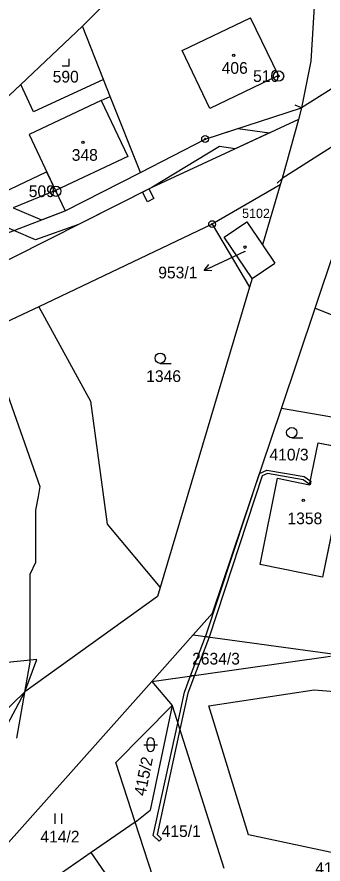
# Model space of a CAD drawing. Extents: x -439246 to -433691, y -1130252 to -1121148.
# Drawn here: x -437746.8 to -437702.2, y -1124070.1 to -1123946.9 of the extents above; entities that cross this region are included whole.
import ezdxf

# ---------------------------------------------------------------- set-up
doc = ezdxf.new("R2010")
doc.units = 0
for name, color, linetype in [('Vrstva 1', 7, 'Continuous'), ('Vrstva 16', 7, 'Continuous'), ('Vrstva 17', 7, 'Continuous'), ('Vrstva 18', 7, 'Continuous'), ('Vrstva 19', 7, 'Continuous'), ('Vrstva 24', 7, 'Continuous'), ('Vrstva 25', 7, 'Continuous'), ('Vrstva 26', 7, 'Continuous'), ('Vrstva 3', 7, 'Continuous'), ('Vrstva 30', 7, 'Continuous'), ('Vrstva 37', 7, 'Continuous'), ('Vrstva 4', 7, 'Continuous'), ('Vrstva 52', 7, 'Continuous')]:
    doc.layers.add(name, color=color, linetype=linetype)

msp = doc.modelspace()

# ---------------------------------------------------------------- linework, layer by layer
at = {"layer": 'Vrstva 1'}
for p, q in [((-437705.84, -1123961.83), (-437708.21, -1123970.37)), ((-437703.39, -1123989.26), (-437690.8, -1123994.18)), ((-437704.24, -1124014.94), (-437702.97, -1124008.81)), ((-437702.97, -1124008.81), (-437698.5, -1124009.7)), ((-437698.5, -1124009.7), (-437702.33, -1124028.36)), ((-437711.41, -1124026.51), (-437708.88, -1124013.98)), ((-437708.88, -1124013.98), (-437704.24, -1124014.94)), ((-437702.33, -1124028.36), (-437711.41, -1124026.51))]:
    msp.add_line(p, q, dxfattribs=at)
for points in [[(-437737.21, -1123948.27), (-437731.59, -1123942.56)], [(-437703.45, -1123943.76), (-437704.03, -1123953.31)], [(-437722.72, -1123951.8), (-437712.79, -1123947.02)], [(-437708.74, -1123955.41), (-437712.79, -1123947.02)], [(-437746.2, -1123956.71), (-437737.21, -1123948.27)], [(-437734.16, -1123955.99), (-437737.21, -1123948.27)], [(-437718.71, -1123960.21), (-437722.72, -1123951.8)], [(-437704.03, -1123953.31), (-437705.37, -1123960.14)], [(-437708.74, -1123955.41), (-437718.71, -1123960.21)], [(-437765.45, -1123974.78), (-437746.2, -1123956.71)], [(-437744.35, -1123960.7), (-437746.2, -1123956.71)], [(-437734.16, -1123955.99), (-437744.35, -1123960.7)], [(-437733.19, -1123958.45), (-437734.16, -1123955.99)], [(-437734.49, -1123959.06), (-437745, -1123964.01)], [(-437734.49, -1123959.06), (-437733.19, -1123958.45)], [(-437728.8, -1123969.53), (-437733.19, -1123958.45)], [(-437719.39, -1123964.65), (-437705.37, -1123960.14)], [(-437705.37, -1123960.14), (-437705.84, -1123961.83)], [(-437705.84, -1123961.83), (-437727.13, -1123971.68)], [(-437745, -1123964.01), (-437741.16, -1123972.15)], [(-437728.8, -1123969.53), (-437719.39, -1123964.65)], [(-437739.77, -1123975.1), (-437728.8, -1123969.53)], [(-437708.48, -1123971.32), (-437718.38, -1123977.03)], [(-437708.48, -1123971.32), (-437711.07, -1123980.02)], [(-437708.21, -1123970.37), (-437708.48, -1123971.32)], [(-437727.13, -1123971.68), (-437762.43, -1123989.47)], [(-437741.16, -1123972.15), (-437739.77, -1123975.1)], [(-437702.36, -1123986.19), (-437697.83, -1123972.76)], [(-437758.83, -1123982.4), (-437739.77, -1123975.1)], [(-437718.38, -1123977.03), (-437743.6, -1123989.04)], [(-437718.38, -1123977.03), (-437712.92, -1123986.21)], [(-437712.54, -1123984.95), (-437716.62, -1123978.94), (-437713.33, -1123976.7), (-437711.07, -1123980.02)], [(-437711.07, -1123980.02), (-437709.25, -1123982.71)], [(-437712.54, -1123984.95), (-437709.25, -1123982.71)], [(-437712.54, -1123984.95), (-437712.92, -1123986.21)], [(-437712.92, -1123986.21), (-437725.93, -1124029.85)], [(-437703.39, -1123989.26), (-437702.36, -1123986.19)], [(-437743.6, -1123989.04), (-437748.4, -1123991.32)], [(-437743.6, -1123989.04), (-437736.06, -1124002.75)], [(-437708.3, -1124003.84), (-437703.39, -1123989.26)], [(-437736.06, -1124002.75), (-437733.66, -1124020.65)], [(-437718.32, -1124033.59), (-437708.3, -1124003.84)], [(-437693.14, -1124006.46), (-437708.3, -1124003.84)], [(-437733.66, -1124020.65), (-437725.93, -1124029.85)], [(-437725.93, -1124029.85), (-437726.32, -1124031.15)], [(-437726.32, -1124031.15), (-437745.62, -1124045.03)], [(-437721.13, -1124036.75), (-437718.32, -1124033.59)], [(-437727.15, -1124043.5), (-437721.13, -1124036.75)], [(-437721.13, -1124036.75), (-437699.47, -1124039.7)], [(-437743.88, -1124040.31), (-437755.3, -1124041.5)], [(-437745.62, -1124045.03), (-437743.88, -1124040.31)], [(-437727.15, -1124043.5), (-437701.18, -1124039.81)], [(-437749.15, -1124068.21), (-437727.15, -1124043.5)], [(-437727.15, -1124043.5), (-437724.18, -1124047.01)], [(-437745.62, -1124045.03), (-437770.58, -1124069.24)], [(-437764.15, -1124079.88), (-437745.62, -1124045.03)], [(-437718.87, -1124047.04), (-437703.55, -1124044.75)], [(-437703.55, -1124044.75), (-437689.8, -1124045.86)], [(-437732.36, -1124055.29), (-437724.18, -1124047.01)], [(-437724.18, -1124047.01), (-437727.38, -1124062.21)], [(-437724.18, -1124047.01), (-437716.69, -1124070.66)], [(-437713.11, -1124065.79), (-437718.87, -1124047.04)], [(-437729.55, -1124063.95), (-437732.36, -1124055.29)], [(-437729.55, -1124063.95), (-437727.38, -1124062.21)], [(-437729.55, -1124063.95), (-437735.96, -1124068.38)], [(-437726.31, -1124073.93), (-437729.55, -1124063.95)], [(-437675.07, -1124073.91), (-437713.11, -1124065.79)], [(-437735.96, -1124068.38), (-437746.02, -1124075.33)], [(-437731.38, -1124075.04), (-437735.96, -1124068.38)]]:
    msp.add_lwpolyline(points, dxfattribs=at)
at = {"layer": 'Vrstva 16'}
msp.add_line((-437716.82, -1123982.51), (-437719.54, -1123983.78), dxfattribs=at)
for points in [[(-437713.61, -1123981.02), (-437716.82, -1123982.51)], [(-437718.42, -1123983.81), (-437719.54, -1123983.78), (-437718.84, -1123982.9)]]:
    msp.add_lwpolyline(points, dxfattribs=at)
at = {"layer": 'Vrstva 24'}
for centre, radius in [((-437708.72, -1123955.5), 0.75), ((-437708.72, -1123955.5), 0.1), ((-437719.39, -1123964.65), 0.5), ((-437719.39, -1123964.65), 0.1), ((-437741.12, -1123972.24), 0.75), ((-437741.12, -1123972.24), 0.1), ((-437718.38, -1123977.03), 0.5), ((-437718.38, -1123977.03), 0.1)]:
    msp.add_circle(centre, radius, dxfattribs=at)
at = {"layer": 'Vrstva 25'}
for p, q in [((-437725.93, -1123997.27), (-437724.33, -1123997.27)), ((-437706.8, -1124008.09), (-437705.2, -1124008.09)), ((-437728.32, -1124052.7), (-437726.32, -1124052.7)), ((-437727.82, -1124053.2), (-437727.82, -1124052.2)), ((-437726.82, -1124052.2), (-437726.82, -1124053.2)), ((-437741.21, -1124064.22), (-437741.21, -1124062.72)), ((-437740.21, -1124064.22), (-437740.21, -1124062.72))]:
    msp.add_line(p, q, dxfattribs=at)
msp.add_lwpolyline([(-437740.18, -1123953.99), (-437739.18, -1123953.99), (-437739.18, -1123952.99)], dxfattribs=at)
for centre, radius in [((-437715.24, -1123952.47), 0.175), ((-437737.16, -1123965.12), 0.175), ((-437713.6, -1123980.37), 0.175), ((-437725.93, -1123996.52), 0.75), ((-437706.8, -1124007.34), 0.75), ((-437705.13, -1124017.18), 0.175)]:
    msp.add_circle(centre, radius, dxfattribs=at)
for centre, start, end in [((-437727.32, -1124052.2), 0, 180), ((-437727.32, -1124053.2), 180, 0)]:
    msp.add_arc(centre, 0.5, start, end, dxfattribs=at)
at = {"layer": 'Vrstva 26'}
for p, q in [((-437705.37, -1123960.14), (-437706.29, -1123959.74)), ((-437708.21, -1123970.37), (-437708.92, -1123971.08))]:
    msp.add_line(p, q, dxfattribs=at)
at = {"layer": 'Vrstva 3'}
for points in [[(-437722.72, -1123951.8), (-437712.79, -1123947.02)], [(-437708.74, -1123955.41), (-437712.79, -1123947.02)], [(-437718.71, -1123960.21), (-437722.72, -1123951.8)], [(-437708.74, -1123955.41), (-437718.71, -1123960.21)], [(-437734.49, -1123959.06), (-437745, -1123964.01)], [(-437734.49, -1123959.06), (-437730.65, -1123967.2)], [(-437745, -1123964.01), (-437741.16, -1123972.15)], [(-437730.65, -1123967.2), (-437741.16, -1123972.15)], [(-437712.54, -1123984.95), (-437716.62, -1123978.94), (-437713.33, -1123976.7), (-437711.07, -1123980.02)], [(-437711.07, -1123980.02), (-437709.25, -1123982.71)], [(-437712.54, -1123984.95), (-437709.25, -1123982.71)], [(-437704.24, -1124014.94), (-437702.97, -1124008.81)], [(-437702.97, -1124008.81), (-437698.5, -1124009.7)], [(-437698.5, -1124009.7), (-437702.33, -1124028.36)], [(-437711.41, -1124026.51), (-437708.88, -1124013.98)], [(-437708.88, -1124013.98), (-437704.24, -1124014.94)], [(-437702.33, -1124028.36), (-437711.41, -1124026.51)]]:
    msp.add_lwpolyline(points, dxfattribs=at)
at = {"layer": 'Vrstva 30'}
for p, q in [((-437727.76, -1123973.77), (-437728.48, -1123972.36)), ((-437727.59, -1123971.91), (-437726.87, -1123973.31)), ((-437726.87, -1123973.31), (-437727.76, -1123973.77))]:
    msp.add_line(p, q, dxfattribs=at)
for points in [[(-437749.39, -1123977.05), (-437750.39, -1123978.91), (-437759.28, -1123981.89), (-437761.4, -1123979.44), (-437752.47, -1123976.45), (-437750.83, -1123973.38), (-437742.46, -1123969.4), (-437741.16, -1123972.15), (-437747.31, -1123974.67), (-437743.19, -1123976.41), (-437739.77, -1123975.1), (-437728.8, -1123969.53), (-437719.39, -1123964.65), (-437714.62, -1123963.12), (-437710.03, -1123963.77), (-437715.02, -1123966.08), (-437717.31, -1123965.76), (-437727.13, -1123971.68), (-437737.8, -1123977.06), (-437744.05, -1123979.3), (-437747.23, -1123977.96), (-437749.39, -1123977.05)], [(-437728.48, -1123972.36), (-437727.59, -1123971.91)], [(-437711.08, -1124013.63), (-437718.83, -1124037.06), (-437719.34, -1124036.99), (-437719.3, -1124036.89), (-437711.47, -1124013.26), (-437710.4, -1124012.77), (-437704.97, -1124013.71), (-437704.03, -1124014.37), (-437704.14, -1124014.91), (-437705.16, -1124014.18), (-437710.34, -1124013.28), (-437711.08, -1124013.63)], [(-437718.83, -1124037.06), (-437720.93, -1124042.62), (-437721.5, -1124042.7), (-437719.34, -1124036.99), (-437718.83, -1124037.06)], [(-437723.07, -1124050.51), (-437726.38, -1124065.74), (-437725.74, -1124066.38), (-437726.09, -1124066.73), (-437726.93, -1124065.9), (-437723.37, -1124049.55), (-437722.4, -1124045.06), (-437721.5, -1124042.7), (-437720.93, -1124042.62), (-437721.92, -1124045.2), (-437723.07, -1124050.51)]]:
    msp.add_lwpolyline(points, dxfattribs=at)
at = {"layer": 'Vrstva 37'}
for centre in [(-437715.24, -1123952.47), (-437737.16, -1123965.12), (-437713.6, -1123980.37), (-437705.13, -1124017.18)]:
    msp.add_circle(centre, 0.175, dxfattribs=at)
at = {"layer": 'Vrstva 4'}
for points in [[(-437692.44, -1123951.97), (-437705.37, -1123960.14)], [(-437734.49, -1123959.06), (-437730.65, -1123967.2)], [(-437692.77, -1123960.61), (-437708.21, -1123970.37)], [(-437730.65, -1123967.2), (-437741.16, -1123972.15)]]:
    msp.add_lwpolyline(points, dxfattribs=at)
at = {"layer": 'Vrstva 52'}
msp.add_lwpolyline([(-437748.78, -1124000), (-437743.42, -1124015.19), (-437743.69, -1124016.62), (-437744.05, -1124018.59), (-437744.05, -1124026.24), (-437744.9, -1124027.94), (-437744.9, -1124040.42), (-437744.9, -1124040.69), (-437745.65, -1124045.06), (-437745.67, -1124045.13), (-437746.82, -1124051.74)], dxfattribs=at)

# ---------------------------------------------------------------- texts
at = {"layer": 'Vrstva 16'}
msp.add_text('953/1', height=1.7, dxfattribs=at).set_placement((-437726.21, -1123984.91))
at = {"layer": 'Vrstva 17'}
for s, p in [('510', (-437712.42, -1123956.35)), ('509', (-437745.04, -1123973.09))]:
    msp.add_text(s, height=1.7, dxfattribs=at).set_placement(p)
at = {"layer": 'Vrstva 18'}
for s, height, p in [('5102', 1.36, (-437714.02, -1123976.14)), ('1346', 1.7, (-437727.96, -1123999.97)), ('410/3', 1.7, (-437710.04, -1124011.38)), ('2634/3', 1.7, (-437721.29, -1124041.05)), ('414/2', 1.7, (-437743.35, -1124066.92)), ('415/1', 1.7, (-437725.72, -1124066.12)), ('416/1', 1.7, (-437703.38, -1124071.49))]:
    msp.add_text(s, height=height, dxfattribs=at).set_placement(p)
msp.add_text('415/2', height=1.7, rotation=78.6956, dxfattribs=at).set_placement((-437728.08, -1124060.24))
at = {"layer": 'Vrstva 19'}
for s, height, p in [('406', 1.7, (-437716.99, -1123955.17)), ('590', 1.7, (-437741.56, -1123956.44)), ('348', 1.7, (-437738.79, -1123967.82)), ('953/1', 0.1, (-437713.78, -1123981.02)), ('1358', 1.7, (-437707.42, -1124020.65))]:
    msp.add_text(s, height=height, dxfattribs=at).set_placement(p)

doc.saveas('drawing.dxf')
